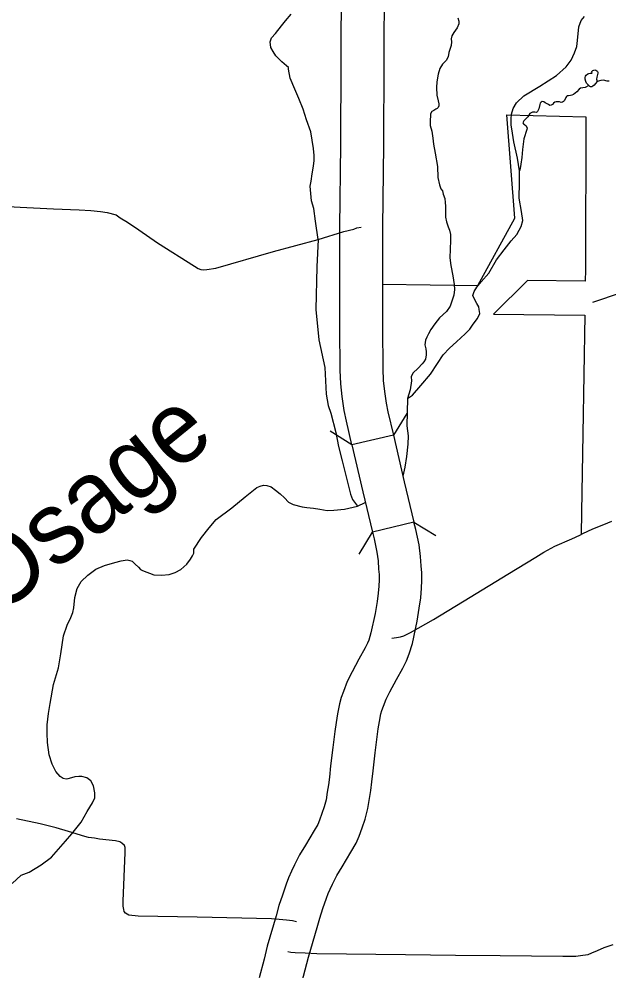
# Model space of a CAD drawing. Extents: x 670147 to 673275, y 705573 to 707613.
# Drawn here: x 671245.2 to 671314.4, y 706470.8 to 706582.5 of the extents above; entities that cross this region are included whole.
import ezdxf

# ---------------------------------------------------------------- set-up
doc = ezdxf.new("R2010")
doc.units = 0
for name, color, linetype in [('10', 7, 'Continuous'), ('33', 7, 'Continuous'), ('34', 7, 'Continuous'), ('35', 7, 'Continuous'), ('37', 7, 'Continuous'), ('6', 7, 'Continuous')]:
    doc.layers.add(name, color=color, linetype=linetype)

msp = doc.modelspace()

# ---------------------------------------------------------------- linework, layer by layer
at = {"layer": '10'}
for points in [[(671289.14, 706533.67), (671284.27, 706532.54), (671283.63, 706535.29), (671283.36, 706536.57), (671283.14, 706538.19), (671282.98, 706539.7), (671282.89, 706541.3), (671282.86, 706546.3), (671282.88, 706558.07), (671282.99, 706567.75), (671283.06, 706587.13), (671283.03, 706591.5), (671283.33, 706604.51), (671283.49, 706608.19), (671283.73, 706628.51), (671283.76, 706641.41), (671283.77, 706649.45), (671283.84, 706659.29), (671283.85, 706664.07), (671283.93, 706673.45), (671284.03, 706683.56), (671284.06, 706686.81), (671284.08, 706689.36)], [(671289.08, 706689.36), (671289.06, 706686.77), (671289.03, 706683.51), (671288.93, 706673.4), (671288.85, 706664.04), (671288.84, 706659.27), (671288.77, 706649.43), (671288.76, 706641.39), (671288.73, 706628.47), (671288.49, 706608.05), (671288.32, 706604.34), (671288.03, 706591.47), (671288.06, 706587.14), (671287.99, 706567.71), (671287.88, 706558.04), (671287.86, 706546.31), (671287.89, 706541.45), (671287.96, 706540.09), (671288.1, 706538.8), (671288.29, 706537.42), (671288.51, 706536.38), (671289.14, 706533.67)], [(671289.14, 706533.67), (671290.41, 706528.19)], [(671284.27, 706532.54), (671285.55, 706527.01)], [(671290.41, 706528.19), (671291.56, 706523.45)], [(671285.55, 706527.01), (671286.7, 706522.27)], [(671291.56, 706523.45), (671286.7, 706522.27), (671286.88, 706521.5), (671287.21, 706519.94), (671287.35, 706518.92), (671287.42, 706517.95), (671287.47, 706517.31), (671287.47, 706516.69), (671287.44, 706515.97), (671287.38, 706515.14), (671287.24, 706514.16), (671287.01, 706512.75), (671286.52, 706510.47), (671286.27, 706509.63), (671286.13, 706509.26), (671285.84, 706508.71), (671285.1, 706507.38), (671284.31, 706505.89), (671283.72, 706504.77), (671283.28, 706503.6), (671283.03, 706502.89), (671282.82, 706502.16), (671282.59, 706500.97), (671282.42, 706499.97), (671282.29, 706498.9), (671282.05, 706497.02), (671281.79, 706494.89), (671281.65, 706493.56), (671281.54, 706492.67), (671281.4, 706491.8), (671281.27, 706490.91), (671281.03, 706490.07), (671280.77, 706489.27), (671280.47, 706488.49), (671280.27, 706488.01), (671279.85, 706487.28), (671278.83, 706485.59), (671278.15, 706484.44), (671277.55, 706483.28), (671277.18, 706482.54), (671276.83, 706481.73), (671276.59, 706481.02), (671276.13, 706479.73), (671275.73, 706478.48), (671275.39, 706477.29), (671274.36, 706473.73), (671273.98, 706472.2), (671273.39, 706470.02)], [(671278.22, 706468.71), (671278.81, 706470.94), (671279.19, 706472.42), (671280.2, 706475.91), (671280.52, 706477.03), (671280.87, 706478.14), (671281.3, 706479.37), (671281.49, 706479.92), (671281.72, 706480.43), (671282.01, 706481.01), (671282.53, 706482.02), (671283.13, 706483.03), (671284.15, 706484.74), (671284.77, 706485.79), (671285.12, 706486.64), (671285.48, 706487.59), (671285.82, 706488.61), (671286.16, 706489.87), (671286.34, 706491.03), (671286.49, 706491.98), (671286.62, 706492.99), (671286.76, 706494.31), (671287.02, 706496.41), (671287.25, 706498.28), (671287.37, 706499.23), (671287.51, 706500.08), (671287.69, 706500.99), (671287.8, 706501.37), (671287.98, 706501.89), (671288.29, 706502.71), (671288.73, 706503.55), (671289.5, 706505), (671290.24, 706506.32), (671290.69, 706507.19), (671291.01, 706508.03), (671291.37, 706509.24), (671291.92, 706511.83), (671292.18, 706513.39), (671292.35, 706514.6), (671292.44, 706515.7), (671292.47, 706516.6), (671292.47, 706517.51), (671292.4, 706518.32), (671292.33, 706519.42), (671292.15, 706520.8), (671291.76, 706522.61), (671291.56, 706523.45)]]:
    msp.add_lwpolyline(points, dxfattribs=at)
at = {"layer": '33'}
for points in [[(671315.85, 706550.36), (671312.49, 706549.21)], [(671288.95, 706509.85), (671289.53, 706509.94), (671289.97, 706510.01), (671290.37, 706510.12), (671291.17, 706510.52), (671293.84, 706512.04), (671298.15, 706514.65), (671302.58, 706517.37), (671305.85, 706519.37), (671306.8, 706519.94), (671308.07, 706520.63), (671310.06, 706521.51), (671311.03, 706521.95), (671311.38, 706522.11), (671312.52, 706522.68), (671313.83, 706523.2), (671314.75, 706523.59)]]:
    msp.add_lwpolyline(points, dxfattribs=at)
at = {"layer": '34'}
for points in [[(671242.55, 706560.57), (671245.39, 706560.41), (671249.29, 706560.2), (671252.28, 706560.11), (671253.65, 706560.01), (671254.81, 706559.9), (671255.58, 706559.76), (671256.63, 706559.5), (671257.12, 706559.17), (671257.98, 706558.64), (671259.3, 706557.76), (671261.49, 706556.23), (671265.83, 706553.49), (671266.25, 706553.2), (671266.55, 706553.08), (671266.86, 706553.05), (671267.28, 706553.08), (671268.31, 706553.26), (671275.08, 706555.22), (671280.34, 706556.63), (671283.35, 706557.55), (671284.5, 706557.84), (671284.86, 706557.97), (671285.38, 706558.05)], [(671277.79, 706476.6), (671277.32, 706476.69), (671276.61, 706476.77), (671275.75, 706476.86), (671274.84, 706476.92), (671266.12, 706477.12), (671259.23, 706477.26), (671258.11, 706477.38), (671257.93, 706477.49), (671257.73, 706477.61), (671257.58, 706477.79), (671257.52, 706478.04), (671257.44, 706478.42), (671257.44, 706479.01), (671257.71, 706484.71), (671257.69, 706485.3), (671257.61, 706485.54), (671257.3, 706485.8), (671257.06, 706485.95), (671256.55, 706486.07), (671254.7, 706486.27), (671254.08, 706486.39), (671253.4, 706486.47), (671252.98, 706486.59), (671251.03, 706487.18), (671249.6, 706487.61), (671248.81, 706487.81), (671247.72, 706488.07), (671244.93, 706488.66)], [(671314.88, 706473.89), (671313.84, 706473.53), (671313.05, 706473.2), (671312.39, 706472.89), (671311.93, 706472.71), (671311.66, 706472.67), (671311.36, 706472.62), (671310.54, 706472.52), (671309, 706472.52), (671301.65, 706472.61), (671296.42, 706472.65), (671290.58, 706472.73), (671280.18, 706472.84), (671278.8, 706472.9), (671277.61, 706472.95), (671277.12, 706472.99), (671276.78, 706473.07)]]:
    msp.add_lwpolyline(points, dxfattribs=at)
at = {"layer": '35'}
for points in [[(671280.32, 706556.61), (671280.01, 706558.75), (671279.81, 706560.24), (671279.53, 706561.14), (671279.47, 706562.01), (671279.39, 706562.86), (671279.5, 706563.45), (671279.62, 706564.32), (671279.78, 706565.22), (671279.87, 706565.87), (671279.87, 706566.46), (671279.78, 706567.3), (671279.64, 706568.26), (671279.45, 706569.24), (671278.97, 706570.65), (671278.58, 706571.91), (671278.07, 706573.15), (671277.57, 706574.23), (671277.06, 706575.55), (671276.84, 706576.59), (671276.84, 706576.79), (671276.61, 706576.99), (671276.08, 706577.46), (671275.38, 706578.14), (671275.04, 706578.65), (671274.76, 706579.15), (671274.7, 706579.8), (671274.84, 706580.25), (671275.32, 706580.78), (671276.02, 706581.68), (671276.5, 706582.27), (671277.15, 706583.06)], [(671290.82, 706537.97), (671291.4, 706538.34), (671292.37, 706539.5), (671293.48, 706540.82), (671294.3, 706542.07), (671295, 706543.07), (671295.73, 706543.88), (671296.55, 706544.6), (671297.55, 706545.53), (671298.11, 706546.11), (671298.5, 706546.67), (671299.02, 706547.35), (671299.3, 706547.95), (671299.22, 706548.41), (671299.17, 706548.71), (671298.92, 706549.12), (671298.62, 706549.68), (671298.47, 706550.05), (671298.62, 706550.5), (671298.95, 706551.03), (671299.45, 706551.66), (671300.33, 706552.66), (671301.25, 706554.21), (671302.13, 706555.39), (671302.96, 706556.45), (671303.63, 706557.18), (671303.88, 706557.7), (671304.13, 706558.13), (671304.33, 706558.85), (671304.18, 706559.91), (671303.88, 706561.46), (671303.93, 706563.29), (671303.93, 706564.67), (671303.71, 706566.17), (671303.26, 706568.07), (671303.11, 706569.1), (671302.96, 706570.05), (671302.96, 706570.78), (671302.98, 706571.33), (671303.18, 706571.98), (671303.58, 706572.65), (671304.46, 706573.48), (671306.31, 706574.6), (671308.27, 706575.83), (671309.42, 706576.88), (671310, 706577.63), (671310.4, 706578.49), (671310.67, 706579.24), (671310.75, 706579.94), (671310.9, 706581.54), (671311.15, 706582.29), (671311.54, 706582.76)], [(671296.71, 706582.61), (671296.82, 706582.23), (671296.82, 706581.9), (671296.61, 706581.45), (671296.23, 706580.88), (671296, 706580.48), (671295.91, 706580.14), (671295.96, 706579.79), (671295.91, 706579.37), (671295.66, 706578.53), (671295.58, 706578.04), (671295.33, 706577.62), (671294.89, 706577.18), (671294.59, 706576.66), (671294.4, 706576.01), (671294.24, 706575.12), (671294.19, 706574.43), (671294.26, 706573.55), (671294.4, 706572.88)], [(671311.72, 706575.14), (671311.64, 706575.41), (671311.63, 706575.61), (671311.67, 706575.77), (671311.76, 706575.9), (671311.93, 706576.04), (671312.06, 706576.09), (671312.22, 706576.12), (671312.36, 706576.12), (671312.42, 706576.13), (671312.45, 706576.17), (671312.42, 706576.23), (671312.43, 706576.31), (671312.55, 706576.43), (671312.65, 706576.48), (671312.78, 706576.5), (671312.9, 706576.48), (671313, 706576.4), (671313.08, 706576.3), (671313.11, 706576.23), (671313.13, 706576.13), (671313.08, 706575.96), (671313.01, 706575.64), (671312.96, 706575.41), (671312.99, 706575.3), (671313.02, 706575.25), (671313.03, 706575.13)], [(671313.03, 706575.13), (671312.85, 706574.9), (671312.7, 706574.72), (671312.52, 706574.59), (671312.41, 706574.53), (671312.34, 706574.51), (671312.25, 706574.52), (671312.17, 706574.57), (671312.05, 706574.67), (671311.93, 706574.81), (671311.79, 706574.96), (671311.72, 706575.14)], [(671314.45, 706575.19), (671314.22, 706575.18), (671313.79, 706575.3), (671313.46, 706575.28), (671313.03, 706575.13)], [(671312.05, 706574.67), (671311.63, 706574.43), (671311.35, 706574.42), (671311.08, 706574.36), (671310.95, 706574.26), (671310.64, 706573.95), (671310.26, 706573.61), (671310.09, 706573.55), (671309.92, 706573.49), (671309.67, 706573.48), (671309.53, 706573.45), (671309.46, 706573.39), (671309.36, 706573.26), (671309.21, 706572.9), (671309.1, 706572.78), (671308.98, 706572.7), (671308.83, 706572.69), (671308.61, 706572.75), (671308.41, 706572.77), (671308.24, 706572.76), (671308.06, 706572.7), (671307.94, 706572.6), (671307.79, 706572.46), (671307.63, 706572.35), (671307.5, 706572.33), (671307.32, 706572.43), (671306.94, 706572.65), (671306.78, 706572.75), (671306.58, 706572.79), (671306.47, 706572.73), (671306.36, 706572.59), (671306.31, 706572.44), (671306.2, 706571.92), (671306.06, 706571.64), (671305.94, 706571.52), (671305.72, 706571.54), (671305.46, 706571.56), (671305.13, 706571.39), (671305.02, 706571.2), (671304.92, 706570.98), (671304.62, 706570.71), (671304.45, 706570.52), (671304.34, 706570.31), (671304.41, 706570.18), (671304.51, 706570.11), (671304.58, 706570.05), (671304.68, 706569.99), (671304.84, 706569.72), (671304.79, 706569.52), (671304.46, 706568.42), (671304.28, 706567.17), (671304.21, 706566.22), (671304.08, 706565.44), (671304.03, 706564.94), (671303.93, 706564.67)], [(671294.4, 706572.88), (671294.47, 706572.52), (671294.49, 706572.27), (671294.4, 706572.08), (671294.28, 706571.97), (671294.11, 706571.89), (671293.9, 706571.76), (671293.67, 706571.62), (671293.5, 706571.34), (671293.48, 706571.13), (671293.46, 706570.6), (671293.46, 706569.97), (671293.67, 706569.3), (671293.77, 706568.48), (671293.84, 706567.81), (671294.05, 706566.74), (671294.3, 706565.16), (671294.34, 706563.9), (671294.57, 706563.02), (671294.72, 706562.56), (671294.89, 706562.31), (671294.99, 706561.93), (671295.18, 706561.42), (671295.2, 706560.94), (671295.24, 706560.54), (671295.26, 706559.24), (671295.37, 706558.68), (671295.58, 706558.09), (671295.73, 706557.69), (671295.83, 706557.18), (671295.85, 706556.49), (671295.75, 706554.48), (671295.87, 706553.58), (671296.12, 706552.36), (671296.27, 706551.35), (671296.33, 706550.76), (671296.25, 706550.1), (671295.79, 706548.79), (671295.39, 706548.17), (671294.55, 706547.41), (671294, 706546.72), (671293.54, 706546.07), (671293.25, 706545.55), (671293.08, 706545.17), (671292.91, 706544.81), (671292.83, 706544.26), (671292.95, 706543.78), (671292.98, 706543.42), (671293, 706543.09), (671292.91, 706542.58), (671292.7, 706542.25), (671292.53, 706542.04)], [(671280.32, 706556.61), (671280.16, 706553.39), (671280.06, 706548.41), (671280.4, 706544.83), (671281.09, 706541.6), (671281.27, 706538.47), (671281.51, 706537.16), (671281.8, 706536.26), (671282.41, 706533.98), (671282.71, 706532.32), (671283.15, 706530.67), (671284.1, 706526.75), (671284.37, 706526.1), (671284.94, 706525.34)], [(671292.53, 706542.04), (671292.07, 706541.53), (671291.44, 706540.95), (671291.23, 706540.5), (671291.27, 706540.02), (671291.13, 706538.99), (671290.82, 706537.97)], [(671290.82, 706537.97), (671290.71, 706534.74), (671290.87, 706533.57), (671290.84, 706532.61), (671290.69, 706531.17), (671290.5, 706529.91), (671290.25, 706528.85)], [(671265.73, 706520.31), (671266.63, 706521.66), (671267.54, 706522.79), (671268.36, 706523.79), (671270.22, 706525.14), (671271.77, 706526.44), (671273.12, 706527.52), (671273.52, 706527.7), (671273.92, 706527.8), (671274.3, 706527.77), (671274.82, 706527.62), (671275.33, 706527.22), (671275.88, 706526.77), (671276.38, 706526.32), (671276.85, 706525.82), (671277.4, 706525.54), (671278.46, 706525.27), (671278.98, 706525.19), (671279.78, 706525.12), (671280.53, 706524.99), (671281.39, 706524.82), (671282.16, 706524.87), (671283.42, 706524.97), (671284.94, 706525.34), (671285.85, 706525.75)], [(671253.33, 706517.24), (671254.26, 706517.96), (671255.28, 706518.39), (671256.48, 706518.73), (671257.23, 706518.94), (671257.93, 706519.03), (671258.24, 706518.98), (671258.52, 706518.87), (671258.88, 706518.53), (671259.26, 706518.17), (671259.49, 706517.92), (671259.72, 706517.8), (671261.06, 706517.28), (671261.95, 706517.26), (671262.85, 706517.33), (671263.55, 706517.55), (671264.21, 706517.89), (671264.93, 706518.55), (671265.34, 706519.12), (671265.59, 706519.5), (671265.73, 706519.82), (671265.73, 706520.31)], [(671244.45, 706481.06), (671245.49, 706482.05), (671246.45, 706482.41), (671247.85, 706483.28), (671249.07, 706484.18), (671250.7, 706486.04), (671251.43, 706486.9), (671252.54, 706488.27), (671253.24, 706489.52), (671253.85, 706490.54), (671254.12, 706491.13), (671254.12, 706491.71), (671253.96, 706492.53), (671253.65, 706493.12), (671253.19, 706493.48), (671252.61, 706493.62), (671252.27, 706493.64), (671251.79, 706493.59), (671251.41, 706493.46), (671250.98, 706493.35), (671250.77, 706493.32), (671250.43, 706493.41), (671250.07, 706493.62), (671249.55, 706494.21), (671249.12, 706495.09), (671248.78, 706496.18), (671248.6, 706497.6), (671248.53, 706498.71), (671248.55, 706499.7), (671248.71, 706501.01), (671248.91, 706502.19), (671249.3, 706504.41), (671249.89, 706506.36), (671250.16, 706508.01), (671250.48, 706510.12), (671250.88, 706511.36), (671251.34, 706512.29), (671251.56, 706512.86), (671251.68, 706513.43), (671251.77, 706514.61), (671252.06, 706515.67), (671252.54, 706516.51), (671253.33, 706517.24)]]:
    msp.add_lwpolyline(points, dxfattribs=at)
at = {"layer": '37'}
for points in [[(671290.72, 706536.22), (671289.14, 706533.67)], [(671284.27, 706532.54), (671281.72, 706534.13)], [(671291.56, 706523.45), (671294.12, 706521.88)], [(671285.13, 706519.71), (671286.7, 706522.27)]]:
    msp.add_lwpolyline(points, dxfattribs=at)
at = {"layer": '6'}
msp.add_lwpolyline([(671287.87, 706551.38), (671299.03, 706551.2), (671303.39, 706559.12), (671302.44, 706571.22), (671311.7, 706570.98), (671311.68, 706552.84), (671311.68, 706552.45), (671311.65, 706552.32), (671311.64, 706551.89), (671311.65, 706551.72), (671311.63, 706551.72), (671304.86, 706551.8), (671300.89, 706547.85), (671311.61, 706547.72), (671311.37, 706533.8), (671311.21, 706524.62), (671311.18, 706522.02)], dxfattribs=at)

# ---------------------------------------------------------------- texts
at = {"layer": '35'}
msp.add_text('Osage', height=8.448, rotation=39.1874, dxfattribs=at).set_placement((671242.66, 706512.13))

doc.saveas('drawing.dxf')
